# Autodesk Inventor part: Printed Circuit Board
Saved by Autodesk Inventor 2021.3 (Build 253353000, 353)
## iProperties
Created: 2023-09
Part Number: Printed Circuit Board
Material: Generic
Document SubType Name: Modeling
Designer: AdminForWorker
Density: 1 g/cm^3
Appearance: Default
Title: Printed Circuit Board
Author: AdminForWorker
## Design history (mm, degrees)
feature "Body1"
body "Solid1"
